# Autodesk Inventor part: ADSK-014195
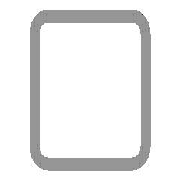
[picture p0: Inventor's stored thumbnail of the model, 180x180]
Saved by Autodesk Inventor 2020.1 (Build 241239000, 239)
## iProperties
_CCFamilyMember: 16
_CCFamilyDisplayName: DIN EN 10210-2 (USAS B17.1 quadratisch) - Rohrleitung — In Klammern angegebene Größen wurden aufgehoben
_FrameMemberDoc: Frame Member File
_Version: 15.0.0
_GetPNFromCC: 1
IsCustomPart: 1
Created: 2019-01
Part Number: ADSK-014195
Material: Stahl, weich
Description: Rohrleitung
Document SubType Name: Modeling
Standard: DIN
Designer: lutzd
Standard Revision: 2006-07
Standards Organization: DIN
Language: de-DE
Size Designation: 50 x 50 x 5
Categories: <MemberInstance><Categories><Category DisplayName="Profile" InternalName="089c4875-fa83-4c05-b084-43b9cc11f5ed" Mnemonic="GRDR"><CategoryParameter DisplayName="
Stock Number: 50 x 50 x 5
Mass: 7948.88 g
Surface Area: 3970.32 cm^2
Volume: 1012.6 cm^3
Density: 7.85 g/cm^3
Appearance: Halbpoliert
G_L: 1168,000 mm
G_W: 50,000 mm
G_H: 50,000 mm
Dimensions: 50x50x1168 mm
Mass: 7,949 kg
DocNumber: ADSK-014176
Folder: .
Title: Profil-Bauteil
Author: lutzd
Revision Number: -
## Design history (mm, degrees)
node "Startebene"
node "Endebene"
sketch "Skizze"
  geometry: L1 (-25, -17.5)-(-25, 17.5); L2 (-17.5, 25)-(17.5, 25); L3 (25, 17.5)-(25, -17.5); L4 (17.5, -25)-(-17.5, -25); L5 (-15, 20)-(15, 20); L6 (20, 15)-(20, -15); L7 (15, -20)-(-15, -20); L8 (-20, -15)-(-20, 15); L9 (0, 37.175)-(0, -37.175) reference; L10 (-37.175, 0)-(37.175, 0) reference; A1 r 7.5 centre (-17.5, -17.5) between (-25, -17.5) and (-17.5, -25); A2 r 7.5 centre (-17.5, 17.5) between (-17.5, 25) and (-25, 17.5); A3 r 7.5 centre (17.5, 17.5) between (25, 17.5) and (17.5, 25); A4 r 7.5 centre (17.5, -17.5) between (17.5, -25) and (25, -17.5); A5 r 5 centre (-15, -15) between (-20, -15) and (-15, -20); A6 r 5 centre (-15, 15) between (-15, 20) and (-20, 15); A7 r 5 centre (15, 15) between (20, 15) and (15, 20); A8 r 5 centre (15, -15) between (15, -20) and (20, -15)
  constraints: 16 end point, 16 point on circle, 16 tangent, 8 centre point, 6 equal radius, 4 parallel, 2 perpendicular, 2 other
  dimensions: "d7" = 7.5 radius of A1 (= G_IR); "d10" = 50 distance between parallel lines of L2 L4 (= G_H); "d11" = 50 distance between parallel lines of L1 L3 (= G_W); "d12" = 5 distance between parallel lines of L3 L6 (= G_T); "d15" = 25 distance between parallel lines of L2 L10 (= 0.5 x d10); "d16" = 25 distance between parallel lines of L9 L3 (= 0.5 x d11); "d19" = 5 radius of A5 (= G_T); "d20" = 5 distance between parallel lines of L4 L7 (= G_T)
extrude "Körper" new body sketch "Skizze" stored distance "d3" = 1168 (= G_L); taper "d4" = 0 deg
node "Driven Length"
  sketch "Sketch3"
    geometry: L1 (0, 0)-(10, 0) reference
    constraints: 2 end point, 1 horizontal
  workplane "Work Plane3"
  sketch "Sketch4"
    geometry: L1 (-2, 0)-(12, 0) reference; L2 (-2, 1168)-(12, 1168) reference
    dimensions: "d18" = 1168 distance between parallel lines of L1 L2 (derived)
workplane "Arbeitsebene4"
feature "Trennen1"
sketch "Skizze5"
  geometry: L1 (0, 35)-(0, 0) reference; L2 (1168, 35)-(1168, 0) reference; L3 (1116.5, 34)-(1149.5, 34); L4 (1149.5, 34)-(1149.5, 1); L5 (1149.5, 1)-(1116.5, 1); L6 (1116.5, 1)-(1116.5, 34); 13 further points; 1 other entity
  constraints: 8 end point, 3 midpoint, 2 coincident, 2 parallel, 1 horizontal, 1 horizontal alignment, 1 perpendicular, 1 vertical alignment, 10 other
  dimensions: "d23" = 25 distance of point (685.5, 17.5) point (660.5, 17.5); "d27" = 35 distance from line of L2 point (1133, 17.5); "d42" = 33 distance of L5.end L3.start; "d43" = 33 distance of L3.start L3.end (= d42); "d63" = 25 distance of point (13.5, 17.5) point (38.5, 17.5); "d85" = 12.5 distance of point (13.5, 17.5) point (26, 17.5) (= 0.5 x d63); "d86" = 26 distance from line of L1 point (26, 17.5); "d87" = 12.5 distance of point (660.5, 17.5) point (673, 17.5) (= 0.5 x d23); "d88" = 495 distance from line of L2 point (673, 17.5)
hole "Bohrung2" sketch "Skizze5" diameter "d35" = 22; stored, may be unused: countersink angle "d39" = 90 deg, drill point angle "d41" = 118 deg; dims "d36" = 16, "d37" = 4, "d38" = 2, "d40" = 22.2
sketch "Skizze6"
  geometry: L1 (-35, 0)-(0, 0) reference; L2 (-17.5, 1168)-(-17.5, 0); L3 (-35, 1168)-(0, 1168) reference; 4 further points
  constraints: 4 point on line, 2 end point, 1 midpoint
  dimensions: "d51" = 25 distance of point (-17.5, 100) point (-17.5, 75); "d52" = 25 distance of point (-17.5, 582) point (-17.5, 557) (= d51); "d53" = 457 distance of point (-17.5, 557) point (-17.5, 100); "d54" = 75 distance from line of point (-17.5, 75) L1
hole "Bohrung4" sketch "Skizze6" at (-17.5, 75), (-17.5, 100), (-17.5, 557), (-17.5, 582) diameter "d55" = 6.647; stored, may be unused: countersink angle "d59" = 90 deg, drill point angle "d61" = 118 deg; dims "d56" = 16, "d57" = 18, "d58" = 4.8, "d60" = 22.2
sketch "Skizze7"
  geometry: L1 (0, 35)-(0, 0) reference; L2 (0, 17.5)-(423.995, 17.5); 5 further points
  constraints: 4 point on line, 2 end point, 1 horizontal, 1 midpoint
  dimensions: "d67" = 41 distance of point (240, 17.5) point (281, 17.5); "d68" = 41 distance of point (408, 17.5) point (367, 17.5) (= d67); "d69" = 127 distance of point (367, 17.5) point (240, 17.5); "d70" = 240 distance from line of L1 point (240, 17.5)
hole "Bohrung5" sketch "Skizze7" at (408, 17.5), (367, 17.5), (281, 17.5), (240, 17.5) diameter "d71" = 6.647; stored, may be unused: countersink angle "d75" = 90 deg, drill point angle "d77" = 118 deg; dims "d72" = 16, "d73" = 4, "d74" = 2, "d76" = 8
hole "Bohrung6" sketch "Skizze5" diameter "d78" = 6.647; stored, may be unused: countersink angle "d82" = 90 deg, drill point angle "d84" = 118 deg; dims "d79" = 16, "d80" = 4, "d81" = 2, "d83" = 8
body "Solid1"
other parameters: "G_W" = 50 [user parameter; used in 1 equation term], "G_H" = 50 [user parameter; used in 1 equation term], "G_T" = 5 [user parameter; used in 3 equation terms], "G_IR" = 7.5 [user parameter; used in 1 equation term], "G_L" = 1168 (= d18) [user parameter; used in 1 equation term], "G_OFFSET_START" = 0 [user parameter; used in 1 equation term], "G_OFFSET_END" = 25 [user parameter; used in 1 equation term], "d13" = 0 (computed from G_OFFSET_START), "d14" = 1168 (= G_OFFSET_END + B_L), "B_L" = 1143 [user parameter; used in 1 equation term], "d17" = 90 deg
